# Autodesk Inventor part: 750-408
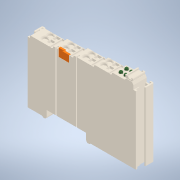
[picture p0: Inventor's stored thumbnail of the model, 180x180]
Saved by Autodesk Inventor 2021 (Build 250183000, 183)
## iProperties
Created: 2026-07
Part Number: 750-408
Material: Generic
Catalog Web Link: www.3dfindit.com
Description: 750-408-4-CHANNEL DIGITAL INPUT MODULE DC 24 V 3,0 ms
Vendor: WAGO
Document SubType Name: Modeling
Designer: psAdmin
Manufacturer: WAGO
Mass: 46.5 g
Surface Area: 195.349 cm^2
Volume: 66.2406 cm^3
Density: 1 g/cm^3
Appearance: PSOLRGB-222-214-201
Category: PARTsolutions
Company: WAGO
Title: 750-408
Author: Cadenas PARTsolutions
Comments: 4-CHANNEL DIGITAL INPUT MODULE DC 24 V 3,0 ms
PSOL_IDENT_0: {$CADENAS_DATA/23d-libs/wago/pg15/serie750/0750-0408_0999-0962.prj},156 {VTYP=3D},{NB=750-408},{LINA=
PSOL_IDENT_1: 750-408},{NN=750-408},{DATE=29.04.2026 11:59:08},{GEOMDATE=18.07.2023 08:27:45},{VERSION=},{LINEID=6
PSOL_IDENT_2: 40},{WBVAR=},{WBNUMERIC=}  {NB=750-408},{LINA=750-408},{KT=DUMMY},{BESTNR=750-408},{INFODE=Info DE},
PSOL_IDENT_3: {INFOEN=Info EN},{QUERSCHNITT1=0.08 - 2.5},{QUERSCHNITT2=28 - 14},{ABISOLIERLAENGE=8 - 9},{HOEHE=64.
PSOL_IDENT_4: 00},{BREITE=12.00},{TIEFE=100.00},{FARBE=lichtgrau},{GEWICHT=46.500},{BEMERKUNGEN=24V DC 3.0 ms  |
PSOL_IDENT_5: negativ schaltend},{RGB=0.87,0.84,0.79,0},{ECLASS71=27-24-26-04},{LINKDE=http://www.wago.com/de/p/75
PSOL_IDENT_6: 0-408},{LINKEN=http://www.wago.com/global/p/750-408},{FILENAME=750-408}
NB: 750-408
NN: 750-408
NT: 4-CHANNEL DIGITAL INPUT MODULE DC 24 V 3,0 ms
NBSYN: $BESTNR.
LINA: 750-408
CATALOG: WAGO
OFFICIAL_STANDARD_NUMBERS: NO
BESTNR: 750-408
INFODE: Info DE
INFOEN: Info EN
QUERSCHNITT1: 0.08 - 2.5
QUERSCHNITT2: 28 - 14
ABISOLIERLAENGE: 8 - 9
HOEHE: 64
BREITE: 12
TIEFE: 100
FARBE: lichtgrau
GEWICHT: 46.5
BEMERKUNGEN: 24V DC 3.0 ms  |  negativ schaltend
ECLASS71: 27-24-26-04
SUPPLIER: WAGO
ARTICLENO: 750-408
BOMINFO: 750-408
CREATOR: CADENAS GmbH
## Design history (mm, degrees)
sketch "Skizze_1"
  geometry: L1 (-32.4, 49.707)-(-32.4, -6.4); L2 (-32.4, -6.4)-(-21.968, -6.4); L3 (-21.968, -6.4)-(-20.7, -7.132); L4 (-17.7, -5.4)-(-17.7, 0); L5 (-17.7, 0)-(17.7, 0); L6 (17.7, 0)-(17.7, -5.4); L7 (20.7, -7.132)-(21.968, -6.4); L8 (21.968, -6.4)-(60, -6.4); L9 (60, -6.4)-(60, 57.922); L10 (60, 57.922)-(58.8, 60); L11 (58.8, 60)-(54.2, 60); L12 (53.54, 59.752)-(52, 58.4); L13 (52, 58.4)-(41.912, 58.4); L14 (41.912, 58.4)-(41.803, 58.354); L15 (41.803, 58.354)-(41.653, 58.199); L16 (42.236, 56.958)-(42.158, 56.766); L17 (42.158, 56.766)-(38.095, 55.042); L18 (38.095, 55.042)-(37.903, 55.119); L19 (37.415, 56.4)-(25.912, 56.4); L20 (25.912, 56.4)-(25.803, 56.354); L21 (25.803, 56.354)-(25.653, 56.199); L22 (26.236, 54.958)-(26.158, 54.766); L23 (26.158, 54.766)-(22.095, 53.042); L24 (22.095, 53.042)-(21.903, 53.119); L25 (21.415, 54.4)-(7.512, 54.4); L26 (7.512, 54.4)-(7.403, 54.354); L27 (7.403, 54.354)-(7.253, 54.199); L28 (7.836, 52.958)-(7.758, 52.766); L29 (7.758, 52.766)-(3.695, 51.042); L30 (3.695, 51.042)-(3.503, 51.119); L31 (3.015, 52.4)-(-10.888, 52.4); L32 (-10.888, 52.4)-(-10.997, 52.354); L33 (-10.997, 52.354)-(-11.147, 52.199); L34 (-10.564, 50.958)-(-10.642, 50.766); L35 (-10.642, 50.766)-(-14.705, 49.042); L36 (-14.705, 49.042)-(-14.897, 49.119); L37 (-15.385, 50.4)-(-32, 50.4); L38 (-32, 50.4)-(-32.4, 49.707); A1 r 2 centre (-19.7, -5.4) between (-20.7, -7.132) and (-17.7, -5.4); A2 r 2 centre (19.7, -5.4) between (17.7, -5.4) and (20.7, -7.132); A3 r 1 centre (54.2, 59) between (54.2, 60) and (53.54, 59.752); A4 r 0.332 centre (41.892, 57.969) between (41.653, 58.199) and (41.844, 57.641); A5 r 0.5 centre (41.772, 57.146) between (42.236, 56.958) and (41.844, 57.641); A6 r 0.5 centre (38.09, 55.583) between (37.684, 55.875) and (37.903, 55.119); A7 r 0.332 centre (37.415, 56.068) between (37.684, 55.875) and (37.415, 56.4); A8 r 0.332 centre (25.892, 55.969) between (25.653, 56.199) and (25.844, 55.641); A9 r 0.5 centre (25.772, 55.146) between (26.236, 54.958) and (25.844, 55.641); A10 r 0.5 centre (22.09, 53.583) between (21.684, 53.875) and (21.903, 53.119); A11 r 0.332 centre (21.415, 54.068) between (21.684, 53.875) and (21.415, 54.4); A12 r 0.331 centre (7.492, 53.969) between (7.253, 54.199) and (7.444, 53.641); A13 r 0.5 centre (7.372, 53.146) between (7.836, 52.958) and (7.444, 53.641); A14 r 0.5 centre (3.69, 51.583) between (3.284, 51.875) and (3.503, 51.119); A15 r 0.332 centre (3.015, 52.068) between (3.284, 51.875) and (3.015, 52.4); A16 r 0.332 centre (-10.908, 51.969) between (-11.147, 52.199) and (-10.956, 51.641); A17 r 0.5 centre (-11.028, 51.146) between (-10.564, 50.958) and (-10.956, 51.641); A18 r 0.5 centre (-14.71, 49.583) between (-15.116, 49.875) and (-14.897, 49.119); A19 r 0.332 centre (-15.385, 50.068) between (-15.116, 49.875) and (-15.385, 50.4)
  constraints: 76 end point, 38 point on circle, 19 centre point
extrude "Extrusion1" join sketch "Skizze_1" distance "d0" = 12; taper "d1" = 0 deg
sketch "Skizze_10"
  geometry: L1 (37.2, 56.4)-(37.981, 54.559); L2 (37.981, 54.559)-(42.693, 56.559); L3 (42.693, 56.559)-(41.912, 58.4); L4 (41.912, 58.4)-(41.342, 58.158); L5 (40.812, 56.847)-(38.971, 56.066); L6 (37.66, 56.595)-(37.2, 56.4); A1 r 1 centre (41.733, 57.238) between (41.342, 58.158) and (40.812, 56.847); A2 r 1 centre (38.051, 55.675) between (38.971, 56.066) and (37.66, 56.595)
  constraints: 12 end point, 4 point on circle, 2 centre point
extrude "Extrusion2" join sketch "Skizze_10" distance "d2" = 0.5; taper "d3" = 0 deg
sketch "Skizze_11"
  geometry: L1 (21.2, 54.4)-(21.981, 52.559); L2 (21.981, 52.559)-(26.693, 54.559); L3 (26.693, 54.559)-(25.912, 56.4); L4 (25.912, 56.4)-(25.342, 56.158); L5 (24.812, 54.847)-(22.971, 54.066); L6 (21.66, 54.595)-(21.2, 54.4); A1 r 1 centre (25.733, 55.238) between (25.342, 56.158) and (24.812, 54.847); A2 r 1 centre (22.051, 53.675) between (22.971, 54.066) and (21.66, 54.595)
  constraints: 12 end point, 4 point on circle, 2 centre point
extrude "Extrusion3" join sketch "Skizze_11" distance "d4" = 0.5; taper "d5" = 0 deg
sketch "Skizze_12"
  geometry: L1 (2.8, 52.4)-(3.581, 50.559); L2 (3.581, 50.559)-(8.293, 52.559); L3 (8.293, 52.559)-(7.512, 54.4); L4 (7.512, 54.4)-(6.942, 54.158); L5 (6.412, 52.847)-(4.571, 52.066); L6 (3.26, 52.595)-(2.8, 52.4); A1 r 1 centre (7.333, 53.238) between (6.942, 54.158) and (6.412, 52.847); A2 r 1 centre (3.651, 51.675) between (4.571, 52.066) and (3.26, 52.595)
  constraints: 12 end point, 4 point on circle, 2 centre point
extrude "Extrusion4" join sketch "Skizze_12" distance "d6" = 0.5; taper "d7" = 0 deg
sketch "Skizze_13"
  geometry: L1 (-15.6, 50.4)-(-14.819, 48.559); L2 (-14.819, 48.559)-(-10.107, 50.559); L3 (-10.107, 50.559)-(-10.888, 52.4); L4 (-10.888, 52.4)-(-11.458, 52.158); L5 (-11.988, 50.847)-(-13.829, 50.066); L6 (-15.14, 50.595)-(-15.6, 50.4); A1 r 1 centre (-11.067, 51.238) between (-11.458, 52.158) and (-11.988, 50.847); A2 r 1 centre (-14.749, 49.675) between (-13.829, 50.066) and (-15.14, 50.595)
  constraints: 12 end point, 4 point on circle, 2 centre point
extrude "Extrusion5" join sketch "Skizze_13" distance "d8" = 0.5; taper "d9" = 0 deg
sketch "Skizze_14"
  geometry: L1 (37.2, 56.4)-(37.981, 54.559); L2 (37.981, 54.559)-(42.693, 56.559); L3 (42.693, 56.559)-(41.912, 58.4); L4 (41.912, 58.4)-(41.342, 58.158); L5 (40.812, 56.847)-(38.971, 56.066); L6 (37.66, 56.595)-(37.2, 56.4); A1 r 1 centre (41.733, 57.238) between (41.342, 58.158) and (40.812, 56.847); A2 r 1 centre (38.051, 55.675) between (38.971, 56.066) and (37.66, 56.595)
  constraints: 12 end point, 4 point on circle, 2 centre point
extrude "Extrusion6" join sketch "Skizze_14" distance "d10" = 0.5; taper "d11" = 0 deg
sketch "Skizze_15"
  geometry: L1 (21.2, 54.4)-(21.981, 52.559); L2 (21.981, 52.559)-(26.693, 54.559); L3 (26.693, 54.559)-(25.912, 56.4); L4 (25.912, 56.4)-(25.342, 56.158); L5 (24.812, 54.847)-(22.971, 54.066); L6 (21.66, 54.595)-(21.2, 54.4); A1 r 1 centre (25.733, 55.238) between (25.342, 56.158) and (24.812, 54.847); A2 r 1 centre (22.051, 53.675) between (22.971, 54.066) and (21.66, 54.595)
  constraints: 12 end point, 4 point on circle, 2 centre point
extrude "Extrusion7" join sketch "Skizze_15" distance "d12" = 0.5; taper "d13" = 0 deg
sketch "Skizze_16"
  geometry: L1 (2.8, 52.4)-(3.581, 50.559); L2 (3.581, 50.559)-(8.293, 52.559); L3 (8.293, 52.559)-(7.512, 54.4); L4 (7.512, 54.4)-(6.942, 54.158); L5 (6.412, 52.847)-(4.571, 52.066); L6 (3.26, 52.595)-(2.8, 52.4); A1 r 1 centre (7.333, 53.238) between (6.942, 54.158) and (6.412, 52.847); A2 r 1 centre (3.651, 51.675) between (4.571, 52.066) and (3.26, 52.595)
  constraints: 12 end point, 4 point on circle, 2 centre point
extrude "Extrusion8" join sketch "Skizze_16" distance "d14" = 0.5; taper "d15" = 0 deg
sketch "Skizze_17"
  geometry: L1 (-15.6, 50.4)-(-14.819, 48.559); L2 (-14.819, 48.559)-(-10.107, 50.559); L3 (-10.107, 50.559)-(-10.888, 52.4); L4 (-10.888, 52.4)-(-11.458, 52.158); L5 (-11.988, 50.847)-(-13.829, 50.066); L6 (-15.14, 50.595)-(-15.6, 50.4); A1 r 1 centre (-11.067, 51.238) between (-11.458, 52.158) and (-11.988, 50.847); A2 r 1 centre (-14.749, 49.675) between (-13.829, 50.066) and (-15.14, 50.595)
  constraints: 12 end point, 4 point on circle, 2 centre point
extrude "Extrusion9" join sketch "Skizze_17" distance "d16" = 0.5; taper "d17" = 0 deg
sketch "Skizze_46"
  geometry: L1 (-7.3, 46.4)-(2.5, 46.4); L2 (2.5, 46.4)-(2.5, 52.4); L3 (2.5, 52.4)-(-7.3, 52.4); L4 (-7.3, 52.4)-(-7.3, 46.4)
  constraints: 8 end point
extrude "Extrusion10" cut sketch "Skizze_46" distance "d18" = 1.9; taper "d19" = 0 deg
sketch "Skizze_47"
  geometry: L1 (-7, 53.4)-(-7, 46.6); L2 (-6.8, 46.4)-(2, 46.4); L3 (2.2, 46.6)-(2.2, 52.2); L4 (2, 52.4)-(-3.3, 52.4); L5 (-3.331, 52.998)-(-2.325, 53.101); L6 (-2.35, 53.6)-(-6.8, 53.6); A1 r 0.2 centre (-6.8, 46.6) between (-7, 46.6) and (-6.8, 46.4); A2 r 0.2 centre (2, 46.6) between (2, 46.4) and (2.2, 46.6); A3 r 0.2 centre (2, 52.2) between (2.2, 52.2) and (2, 52.4); A4 r 0.3 centre (-3.3, 52.7) between (-3.331, 52.998) and (-3.3, 52.4); A5 r 0.25 centre (-2.35, 53.35) between (-2.325, 53.101) and (-2.35, 53.6); A6 r 0.2 centre (-6.8, 53.4) between (-6.8, 53.6) and (-7, 53.4)
  constraints: 12 end point, 12 point on circle, 6 centre point
extrude "Extrusion11" join sketch "Skizze_47" stored distance "d20" = 1.6; taper "d21" = 0 deg
sketch "Skizze_2"
  geometry: L1 (60, 0)-(60, -1.7); L2 (60.5, -1.2)-(61.9, -1.2); L3 (62.4, -1.7)-(62.4, -4.3); L4 (63.8, -4.3)-(63.8, 1.8); L5 (62.8, 2.8)-(61.3, 2.8); L6 (60.8, 2.3)-(60.8, 1.9); L7 (61, 1.7)-(62.2, 1.7); L8 (62.4, 1.5)-(62.4, 0.2); L9 (62.2, 0)-(60, 0); A1 r 0.5 centre (60.5, -1.7) between (60.5, -1.2) and (60, -1.7); A2 r 0.5 centre (61.9, -1.7) between (62.4, -1.7) and (61.9, -1.2); A3 r 0.7 centre (63.1, -4.3) between (62.4, -4.3) and (63.8, -4.3); A4 r 1 centre (62.8, 1.8) between (63.8, 1.8) and (62.8, 2.8); A5 r 0.5 centre (61.3, 2.3) between (61.3, 2.8) and (60.8, 2.3); A6 r 0.2 centre (61, 1.9) between (60.8, 1.9) and (61, 1.7); A7 r 0.2 centre (62.2, 1.5) between (62.4, 1.5) and (62.2, 1.7); A8 r 0.2 centre (62.2, 0.2) between (62.2, 0) and (62.4, 0.2)
  constraints: 18 end point, 16 point on circle, 8 centre point
extrude "Extrusion12" join sketch "Skizze_2" distance "d22" = 60.8; taper "d23" = 0 deg
sketch "Skizze_3"
  geometry: L1 (-34.8, -4.3)-(-34.8, -1.7); L2 (-34.3, -1.2)-(-32.9, -1.2); L3 (-32.4, -1.7)-(-32.4, 0); L4 (-32.4, 0)-(-34.6, 0); L5 (-34.8, 0.2)-(-34.8, 1.5); L6 (-34.6, 1.7)-(-33.4, 1.7); L7 (-33.2, 1.9)-(-33.2, 2.3); L8 (-33.7, 2.8)-(-35.2, 2.8); L9 (-36.2, 1.8)-(-36.2, -4.3); A1 r 0.7 centre (-35.5, -4.3) between (-36.2, -4.3) and (-34.8, -4.3); A2 r 0.5 centre (-34.3, -1.7) between (-34.3, -1.2) and (-34.8, -1.7); A3 r 0.5 centre (-32.9, -1.7) between (-32.4, -1.7) and (-32.9, -1.2); A4 r 0.2 centre (-34.6, 0.2) between (-34.8, 0.2) and (-34.6, 0); A5 r 0.2 centre (-34.6, 1.5) between (-34.6, 1.7) and (-34.8, 1.5); A6 r 0.2 centre (-33.4, 1.9) between (-33.4, 1.7) and (-33.2, 1.9); A7 r 0.5 centre (-33.7, 2.3) between (-33.2, 2.3) and (-33.7, 2.8); A8 r 1 centre (-35.2, 1.8) between (-35.2, 2.8) and (-36.2, 1.8)
  constraints: 18 end point, 16 point on circle, 8 centre point
extrude "Extrusion13" join sketch "Skizze_3" distance "d24" = 54.8; taper "d25" = 0 deg
sketch "Skizze_9"
  geometry: L1 (-34.6, -10.6)-(-34.6, -11.8); L2 (-34.4, -12)-(-32.4, -12); L3 (-32.4, -12)-(-32.4, -7); L4 (-32.4, -7)-(-33, -7); L5 (-33, -7)-(-33, -10.4); L6 (-33, -10.4)-(-34.4, -10.4); A1 r 0.2 centre (-34.4, -11.8) between (-34.6, -11.8) and (-34.4, -12); A2 r 0.2 centre (-34.4, -10.6) between (-34.4, -10.4) and (-34.6, -10.6)
  constraints: 12 end point, 4 point on circle, 2 centre point
extrude "Extrusion14" join sketch "Skizze_9" distance "d26" = 54.8; taper "d27" = 0 deg
sketch "Skizze_8"
  geometry: L1 (60, -7)-(60, -12); L2 (60, -12)-(62, -12); L3 (62.2, -11.8)-(62.2, -10.6); L4 (62, -10.4)-(60.6, -10.4); L5 (60.6, -10.4)-(60.6, -7); L6 (60.6, -7)-(60, -7); A1 r 0.2 centre (62, -11.8) between (62, -12) and (62.2, -11.8); A2 r 0.2 centre (62, -10.6) between (62.2, -10.6) and (62, -10.4)
  constraints: 12 end point, 4 point on circle, 2 centre point
extrude "Extrusion15" join sketch "Skizze_8" distance "d28" = 60.8; taper "d29" = 0 deg
sketch "Skizze_4"
  geometry: L1 (-2.7, 56.4)-(-2.7, 58.4); L2 (-2.7, 58.4)-(-0.6, 58.4); L3 (-0.6, 58.4)-(-0.6, 58); L4 (-0.6, 58)-(-1, 57.6); L5 (-1, 57.6)-(-1, 56.4); L6 (-1, 56.4)-(-2.7, 56.4); L7 (-2.7, 56.4)-(-2.7, 58.4)
  constraints: 14 end point
revolve "Revolution1" sketch "Skizze_4" stored, may be unused: angle "d30" = 360 deg
pattern_linear "Rectangular Pattern1" dims "d33" = 5, "d36" = 0
sketch "Skizze_6"
  geometry: L1 (-2.7, 55.4)-(-2.7, 59.7); L2 (-1.25, 58.25)-(-1.25, 56.42); L3 (-1.25, 56.42)-(-1.15, 56.42); L4 (-1.15, 56.42)-(-1.15, 55.4); L5 (-1.15, 55.4)-(-2.7, 55.4); L6 (-2.7, 55.4)-(-2.7, 59.7); A1 r 1.45 centre (-2.7, 58.25) between (-1.25, 58.25) and (-2.7, 59.7)
  constraints: 12 end point, 2 point on circle, 1 centre point
revolve "Revolution2" sketch "Skizze_6" stored, may be unused: angle "d37" = 360 deg
pattern_linear "Rectangular Pattern2" dims "d40" = 5, "d43" = 0
sketch "Skizze_18"
  geometry: L1 (-2.7, 56.4)-(-2.7, 58.4); L2 (-2.7, 58.4)-(-0.6, 58.4); L3 (-0.6, 58.4)-(-0.6, 58); L4 (-0.6, 58)-(-1, 57.6); L5 (-1, 57.6)-(-1, 56.4); L6 (-1, 56.4)-(-2.7, 56.4); L7 (-2.7, 56.4)-(-2.7, 58.4)
  constraints: 14 end point
revolve "Revolution3" sketch "Skizze_18" stored, may be unused: angle "d44" = 360 deg
pattern_linear "Rectangular Pattern3" dims "d47" = 5, "d50" = 0
sketch "Skizze_20"
  geometry: L1 (-2.7, 55.4)-(-2.7, 59.7); L2 (-1.25, 58.25)-(-1.25, 56.42); L3 (-1.25, 56.42)-(-1.15, 56.42); L4 (-1.15, 56.42)-(-1.15, 55.4); L5 (-1.15, 55.4)-(-2.7, 55.4); L6 (-2.7, 55.4)-(-2.7, 59.7); A1 r 1.45 centre (-2.7, 58.25) between (-1.25, 58.25) and (-2.7, 59.7)
  constraints: 12 end point, 2 point on circle, 1 centre point
revolve "Revolution4" sketch "Skizze_20" stored, may be unused: angle "d51" = 360 deg
pattern_linear "Rectangular Pattern4" dims "d54" = 5, "d57" = 0
sketch "Sketch20"
  geometry: 1 further point
hole "Hole1" sketch "Sketch20" at (3.188, 9.5) diameter "d58" = 4.2; stored, may be unused: countersink angle "d62" = 90 deg, drill point angle "d64" = 0 deg; dims "d59" = 6, "d60" = 5.4, "d61" = 2, "d63" = 2
pattern_linear "Rectangular Pattern5" dims "d67" = 5, "d70" = 0
sketch "Skizze_24"
  geometry: L1 (-2.5, 54.4)-(-2.5, 56.4); L2 (-2.5, 56.4)-(-1.2, 56.4); L3 (-1.2, 56.4)-(-1.4, 55.8); L4 (-1.4, 55.8)-(-1.4, 54.4); L5 (-1.4, 54.4)-(-2.5, 54.4); L6 (-2.5, 54.4)-(-2.5, 56.4)
  constraints: 12 end point
revolve "Revolution5" sketch "Skizze_24" stored, may be unused: angle "d71" = 360 deg
pattern_linear "Rectangular Pattern6" dims "d74" = 5, "d77" = 0
sketch "Skizze_26"
  geometry: L1 (-4.5, 54.4)-(-0.8, 54.4); L2 (-0.8, 54.4)-(-0.8, 56.4); L3 (-0.8, 56.4)-(-4.5, 56.4); L4 (-4.5, 56.4)-(-4.5, 54.4)
  constraints: 8 end point
extrude "Extrusion16" cut sketch "Skizze_26" distance "d78" = 3.8; taper "d79" = 0 deg
pattern_linear "Rectangular Pattern7" dims "d82" = 5, "d85" = 0
sketch "Sketch23"
  geometry: 1 further point
hole "Hole2" sketch "Sketch23" at (5.588, 9.5) diameter "d86" = 4.2; stored, may be unused: countersink angle "d90" = 90 deg, drill point angle "d92" = 0 deg; dims "d87" = 6, "d88" = 5.4, "d89" = 2, "d91" = 2
pattern_linear "Rectangular Pattern8" dims "d95" = 5, "d98" = 0
sketch "Skizze_30"
  geometry: L1 (-2.5, 52.4)-(-2.5, 54.4); L2 (-2.5, 54.4)-(-1.2, 54.4); L3 (-1.2, 54.4)-(-1.4, 53.8); L4 (-1.4, 53.8)-(-1.4, 52.4); L5 (-1.4, 52.4)-(-2.5, 52.4); L6 (-2.5, 52.4)-(-2.5, 54.4)
  constraints: 12 end point
revolve "Revolution6" sketch "Skizze_30" stored, may be unused: angle "d99" = 360 deg
pattern_linear "Rectangular Pattern9" dims "d102" = 5, "d105" = 0
sketch "Skizze_32"
  geometry: L1 (-4.5, 52.4)-(-0.8, 52.4); L2 (-0.8, 52.4)-(-0.8, 54.4); L3 (-0.8, 54.4)-(-4.5, 54.4); L4 (-4.5, 54.4)-(-4.5, 52.4)
  constraints: 8 end point
extrude "Extrusion17" cut sketch "Skizze_32" distance "d106" = 3.8; taper "d107" = 0 deg
pattern_linear "Rectangular Pattern10" dims "d110" = 5, "d113" = 0
sketch "Sketch26"
  geometry: 1 further point
hole "Hole3" sketch "Sketch26" at (5.588, 9.5) diameter "d114" = 4.2; stored, may be unused: countersink angle "d118" = 90 deg, drill point angle "d120" = 0 deg; dims "d115" = 6, "d116" = 5.4, "d117" = 2, "d119" = 2
pattern_linear "Rectangular Pattern11" dims "d123" = 5, "d126" = 0
sketch "Skizze_36"
  geometry: L1 (-2.5, 50.4)-(-2.5, 52.4); L2 (-2.5, 52.4)-(-1.2, 52.4); L3 (-1.2, 52.4)-(-1.4, 51.8); L4 (-1.4, 51.8)-(-1.4, 50.4); L5 (-1.4, 50.4)-(-2.5, 50.4); L6 (-2.5, 50.4)-(-2.5, 52.4)
  constraints: 12 end point
revolve "Revolution7" sketch "Skizze_36" stored, may be unused: angle "d127" = 360 deg
pattern_linear "Rectangular Pattern12" dims "d130" = 5, "d133" = 0
sketch "Skizze_38"
  geometry: L1 (-4.5, 50.4)-(-0.8, 50.4); L2 (-0.8, 50.4)-(-0.8, 52.4); L3 (-0.8, 52.4)-(-4.5, 52.4); L4 (-4.5, 52.4)-(-4.5, 50.4)
  constraints: 8 end point
extrude "Extrusion18" cut sketch "Skizze_38" distance "d134" = 3.8; taper "d135" = 0 deg
pattern_linear "Rectangular Pattern13" dims "d138" = 5, "d141" = 0
sketch "Sketch29"
  geometry: 1 further point
hole "Hole4" sketch "Sketch29" at (8.3, 9.5) diameter "d142" = 4.2; stored, may be unused: countersink angle "d146" = 90 deg, drill point angle "d148" = 0 deg; dims "d143" = 6, "d144" = 5.4, "d145" = 2, "d147" = 2
pattern_linear "Rectangular Pattern14" dims "d151" = 5, "d154" = 0
sketch "Skizze_42"
  geometry: L1 (-2.5, 48.4)-(-2.5, 50.4); L2 (-2.5, 50.4)-(-1.2, 50.4); L3 (-1.2, 50.4)-(-1.4, 49.8); L4 (-1.4, 49.8)-(-1.4, 48.4); L5 (-1.4, 48.4)-(-2.5, 48.4); L6 (-2.5, 48.4)-(-2.5, 50.4)
  constraints: 12 end point
revolve "Revolution8" sketch "Skizze_42" stored, may be unused: angle "d155" = 360 deg
pattern_linear "Rectangular Pattern15" dims "d158" = 5, "d161" = 0
sketch "Skizze_44"
  geometry: L1 (-4.5, 48.4)-(-0.8, 48.4); L2 (-0.8, 48.4)-(-0.8, 50.4); L3 (-0.8, 50.4)-(-4.5, 50.4); L4 (-4.5, 50.4)-(-4.5, 48.4)
  constraints: 8 end point
extrude "Extrusion19" cut sketch "Skizze_44" distance "d162" = 3.8; taper "d163" = 0 deg
pattern_linear "Rectangular Pattern16" dims "d166" = 5, "d169" = 0
sketch "Skizze_48"
  geometry: L1 (52.1, 61.9)-(52.5, 61.9); L2 (52.5, 61.9)-(52.5, 60.5); L3 (53, 60)-(58.4, 60); L4 (58.9, 60.5)-(58.9, 61.9); L5 (58.9, 61.9)-(59.3, 61.9); L6 (58.8, 62.4)-(58.1, 62.4); L7 (57.86, 61.92)-(58.1, 61.6); L8 (57.7, 60.8)-(53.7, 60.8); L9 (53.3, 61.6)-(53.54, 61.92); L10 (53.3, 62.4)-(52.6, 62.4); A1 r 0.5 centre (53, 60.5) between (52.5, 60.5) and (53, 60); A2 r 0.5 centre (58.4, 60.5) between (58.4, 60) and (58.9, 60.5); A3 r 0.5 centre (58.8, 61.9) between (59.3, 61.9) and (58.8, 62.4); A4 r 0.3 centre (58.1, 62.1) between (58.1, 62.4) and (57.86, 61.92); A5 r 0.5 centre (57.7, 61.3) between (57.7, 60.8) and (58.1, 61.6); A6 r 0.5 centre (53.7, 61.3) between (53.3, 61.6) and (53.7, 60.8); A7 r 0.3 centre (53.3, 62.1) between (53.54, 61.92) and (53.3, 62.4); A8 r 0.5 centre (52.6, 61.9) between (52.6, 62.4) and (52.1, 61.9)
  constraints: 20 end point, 16 point on circle, 8 centre point
extrude "Extrusion20" join sketch "Skizze_48" stored distance "d170" = 11.2; taper "d171" = 0 deg
sketch "Skizze_49"
  geometry: L1 (53.2, 62.4)-(53.2, 60.8); L2 (53.2, 60.8)-(55.1, 60.8); L3 (55.1, 60.8)-(54.87, 61.659); L4 (53.904, 62.4)-(53.2, 62.4); A1 r 1 centre (53.904, 61.4) between (54.87, 61.659) and (53.904, 62.4)
  constraints: 8 end point, 2 point on circle, 1 centre point
extrude "Extrusion21" join sketch "Skizze_49" distance "d172" = 0.6; taper "d173" = 0 deg
sketch "Skizze_50"
  geometry: L1 (56.3, 60.8)-(58.2, 60.8); L2 (58.2, 60.8)-(58.2, 62.4); L3 (58.2, 62.4)-(57.496, 62.4); L4 (56.53, 61.659)-(56.3, 60.8); A1 r 1 centre (57.496, 61.4) between (57.496, 62.4) and (56.53, 61.659)
  constraints: 8 end point, 2 point on circle, 1 centre point
extrude "Extrusion22" join sketch "Skizze_50" distance "d174" = 0.6; taper "d175" = 0 deg
sketch "Sketch_1"
  geometry: L1 (-9.7, -13)-(9.7, -13); L2 (9.7, -13)-(9.7, -9.4); L3 (9.7, -9.4)-(8.7, -9.4); L4 (8.7, -9.4)-(8.7, -12); L5 (8.7, -12)-(-8.7, -12); L6 (-8.7, -12)-(-8.7, -9.4); L7 (-8.7, -9.4)-(-9.7, -9.4); L8 (-9.7, -9.4)-(-9.7, -13)
  constraints: 16 end point
extrude "Extrusion23" cut sketch "Sketch_1" distance "d176" = 65; taper "d177" = 0 deg
sketch "Sketch_2"
  geometry: L1 (8.95, 44.9)-(8.95, 41.3); L2 (8.95, 41.3)-(9.35, 41.3); L3 (9.35, 41.3)-(9.35, 44.9); L4 (9.35, 44.9)-(8.95, 44.9)
  constraints: 8 end point
extrude "Extrusion24" join sketch "Sketch_2" distance "d178" = 2.4; taper "d179" = 0 deg
sketch "Sketch_3"
  geometry: L1 (-9.45, 42.9)-(-9.45, 39.3); L2 (-9.45, 39.3)-(-9.05, 39.3); L3 (-9.05, 39.3)-(-9.05, 42.9); L4 (-9.05, 42.9)-(-9.45, 42.9)
  constraints: 8 end point
extrude "Extrusion25" join sketch "Sketch_3" distance "d180" = 2.4; taper "d181" = 0 deg
node "1_10_XY"
node "1_10_YZ"
node "1_10_ZX"
node "1_10_X"
node "1_10_Y"
node "1_10_Z"
node "1_10_Center"
node "1_11_XY"
node "1_11_YZ"
node "1_11_ZX"
node "1_11_X"
node "1_11_Y"
node "1_11_Z"
node "1_11_Center"
node "1_12_XY"
node "1_12_YZ"
node "1_12_ZX"
node "1_12_X"
node "1_12_Y"
node "1_12_Z"
node "1_12_Center"
node "1_13_XY"
node "1_13_YZ"
node "1_13_ZX"
node "1_13_X"
node "1_13_Y"
node "1_13_Z"
node "1_13_Center"
node "1_14_XY"
node "1_14_YZ"
node "1_14_ZX"
node "1_14_X"
node "1_14_Y"
node "1_14_Z"
node "1_14_Center"
node "1_15_XY"
node "1_15_YZ"
node "1_15_ZX"
node "1_15_X"
node "1_15_Y"
node "1_15_Z"
node "1_15_Center"
node "1_16_XY"
node "1_16_YZ"
node "1_16_ZX"
node "1_16_X"
node "1_16_Y"
node "1_16_Z"
node "1_16_Center"
node "1_17_XY"
node "1_17_YZ"
node "1_17_ZX"
node "1_17_X"
node "1_17_Y"
node "1_17_Z"
node "1_17_Center"
node "1_18_XY"
node "1_18_YZ"
node "1_18_ZX"
node "1_18_X"
node "1_18_Y"
node "1_18_Z"
node "1_18_Center"
node "1_19_XY"
node "1_19_YZ"
node "1_19_ZX"
node "1_19_X"
node "1_19_Y"
node "1_19_Z"
node "1_19_Center"
node "1_2_XY"
node "1_2_YZ"
node "1_2_ZX"
node "1_2_X"
node "1_2_Y"
node "1_2_Z"
node "1_2_Center"
node "1_20_XY"
node "1_20_YZ"
node "1_20_ZX"
node "1_20_X"
node "1_20_Y"
node "1_20_Z"
node "1_20_Center"
node "1_21_XY"
node "1_21_YZ"
node "1_21_ZX"
node "1_21_X"
node "1_21_Y"
node "1_21_Z"
node "1_21_Center"
node "1_22_XY"
node "1_22_YZ"
node "1_22_ZX"
node "1_22_X"
node "1_22_Y"
node "1_22_Z"
node "1_22_Center"
node "1_23_XY"
node "1_23_YZ"
node "1_23_ZX"
node "1_23_X"
node "1_23_Y"
node "1_23_Z"
node "1_23_Center"
node "1_24_XY"
node "1_24_YZ"
node "1_24_ZX"
node "1_24_X"
node "1_24_Y"
node "1_24_Z"
node "1_24_Center"
node "1_25_XY"
node "1_25_YZ"
node "1_25_ZX"
node "1_25_X"
node "1_25_Y"
node "1_25_Z"
node "1_25_Center"
node "1_28_XY"
node "1_28_YZ"
node "1_28_ZX"
node "1_28_X"
node "1_28_Y"
node "1_28_Z"
node "1_28_Center"
node "1_29_XY"
node "1_29_YZ"
node "1_29_ZX"
node "1_29_X"
node "1_29_Y"
node "1_29_Z"
node "1_29_Center"
node "1_3_XY"
node "1_3_YZ"
node "1_3_ZX"
node "1_3_X"
node "1_3_Y"
node "1_3_Z"
node "1_3_Center"
node "1_4_XY"
node "1_4_YZ"
node "1_4_ZX"
node "1_4_X"
node "1_4_Y"
node "1_4_Z"
node "1_4_Center"
node "1_5_XY"
node "1_5_YZ"
node "1_5_ZX"
node "1_5_X"
node "1_5_Y"
node "1_5_Z"
node "1_5_Center"
node "1_6_XY"
node "1_6_YZ"
node "1_6_ZX"
node "1_6_X"
node "1_6_Y"
node "1_6_Z"
node "1_6_Center"
node "1_7_XY"
node "1_7_YZ"
node "1_7_ZX"
node "1_7_X"
node "1_7_Y"
node "1_7_Z"
node "1_7_Center"
node "1_8_XY"
node "1_8_YZ"
node "1_8_ZX"
node "1_8_X"
node "1_8_Y"
node "1_8_Z"
node "1_8_Center"
node "1_9_XY"
node "1_9_YZ"
node "1_9_ZX"
node "1_9_X"
node "1_9_Y"
node "1_9_Z"
node "1_9_Center"
body "Solid1"
other parameters: "d182" = 0, "d183" = 0, "d184" = 0, "d185" = 0, "d186" = 0, "d187" = 0, "d188" = 0, "d189" = 0, "d190" = 0, "d191" = 0, "d192" = 0, "d193" = 0, "d194" = 0, "d195" = 0, "d196" = 0, "d197" = 0, "d198" = 0, "d199" = 0, "d200" = 0, "d201" = 0, "d202" = 0, "d203" = 0, "d204" = 0, "d205" = 0, "d206" = 0, "d207" = 0
